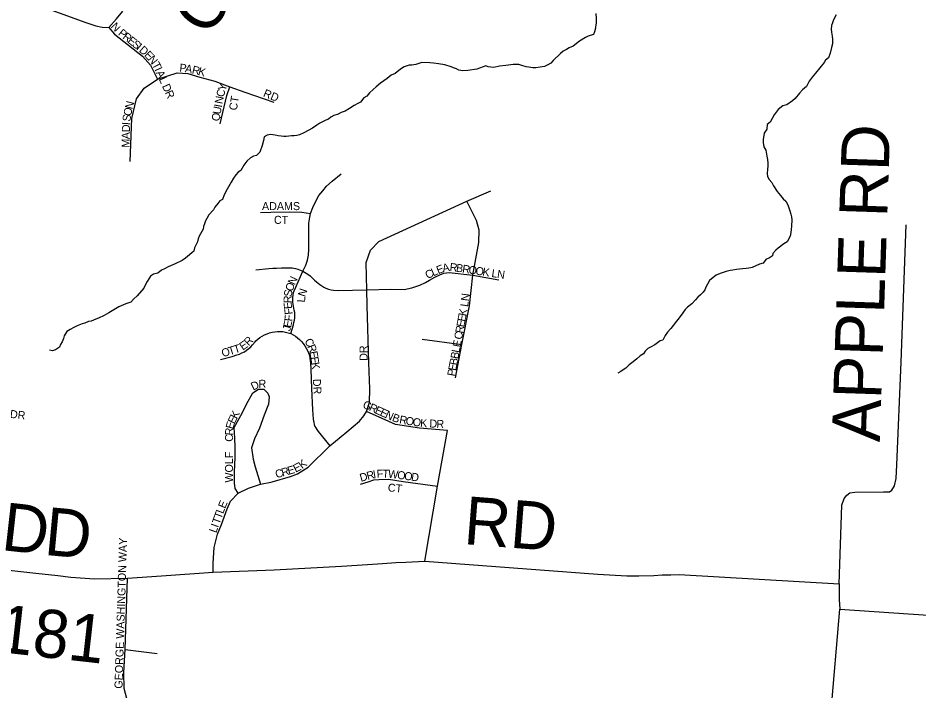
# Model space of a CAD drawing. Extents: x 1310247 to 1664935, y 235267 to 584339.
# Drawn here: x 1479257 to 1484885, y 386965 to 391172 of the extents above; entities that cross this region are included whole.
import ezdxf

# ---------------------------------------------------------------- set-up
doc = ezdxf.new("R2010")
doc.units = 0
for name, color, linetype in [('GM_X_County_Road', 7, 'Continuous'), ('GM_X_County_Road_Text', 7, 'Continuous'), ('GM_X_Minor_River', 7, 'Continuous'), ('GM_X_Township_Road', 7, 'Continuous'), ('GM_X_Township_Road_Text', 7, 'Continuous'), ('GM_X_Township_Subdivision', 7, 'Continuous'), ('GM_X_Township_Subdivision_Text', 7, 'Continuous')]:
    doc.layers.add(name, color=color, linetype=linetype)

msp = doc.modelspace()

# ---------------------------------------------------------------- linework, layer by layer
at = {"layer": 'GM_X_County_Road'}
msp.add_lwpolyline([(1479347, 391264), (1479681.3, 391144.1), (1479744.4, 391123.4), (1479782.5, 391114.5), (1479823.8, 391111.7), (1479871.9, 391165.9), (1479912.2, 391215.7)], dxfattribs=at)
at = {"layer": 'GM_X_Minor_River'}
for points in [[(1482866.9, 391201.2), (1482868.4, 391169), (1482867.9, 391141), (1482863.3, 391100.9), (1482859, 391084.9), (1482852.7, 391069), (1482818.4, 391057.5), (1482802.2, 391049.8), (1482765.7, 391026.3), (1482725, 390995), (1482700.7, 390985.3), (1482682.5, 390975.6), (1482662.2, 390963.9), (1482645.9, 390950.2), (1482601.1, 390906.8), (1482584.7, 390889), (1482566.5, 390879.3), (1482546.2, 390869.6), (1482518, 390864.1), (1482491.9, 390860.6), (1482473.8, 390860.9), (1482447.8, 390865.3), (1482431.8, 390867.6)], [(1484368.3, 391192.9), (1484351.7, 391161.1), (1484345.3, 391141.1), (1484339.1, 391125.2), (1484336.7, 391103.1), (1484338.3, 391083), (1484344, 391058.9), (1484345.6, 391038.8), (1484345.2, 391010.7), (1484338.8, 390988.7), (1484330.1, 390952.7), (1484319.6, 390922.8), (1484301.3, 390909.1), (1484293, 390893.2), (1484266.4, 390861.5), (1484239.7, 390827.9), (1484217.2, 390802.2), (1484198.7, 390776.4), (1484182.1, 390744.6), (1484157.7, 390723), (1484139.2, 390701.2), (1484112.6, 390669.5), (1484096.3, 390653.8), (1484059.8, 390630.3), (1484035.6, 390622.7), (1484005, 390599.2), (1483980.4, 390567.5), (1483955.6, 390521.8), (1483937.2, 390506), (1483934.8, 390478), (1483918.3, 390452.2), (1483911.6, 390412.2), (1483911.3, 390394.1), (1483916.8, 390365.9), (1483928.5, 390345.6), (1483935.9, 390307.4), (1483939.6, 390287.2), (1483941.2, 390265.1), (1483940.9, 390247.1), (1483938.6, 390225), (1483936.1, 390201), (1483939.8, 390180.8), (1483949.5, 390162.6), (1483965.3, 390144.3), (1483977, 390122), (1484000.5, 390087.5), (1484020.1, 390063), (1484037.9, 390042.6), (1484053.7, 390026.3), (1484065.3, 390004), (1484078.8, 389967.7), (1484084.4, 389945.5), (1484088.2, 389929.4), (1484091.9, 389911.2)], [(1482431.8, 390867.6), (1482403.8, 390876.1), (1482385.8, 390880.5), (1482349.7, 390881.1), (1482305.5, 390875.9), (1482265.2, 390870.6), (1482229, 390863.2), (1482210.9, 390865.5), (1482194.9, 390867.8), (1482178.9, 390872.1), (1482162.8, 390866.3), (1482140.6, 390858.7), (1482122.4, 390853), (1482068.1, 390843.9), (1482035.9, 390842.5), (1482011.9, 390846.9), (1481996, 390855.2), (1481978, 390861.5), (1481962.1, 390867.8), (1481924.1, 390878.5), (1481884.1, 390885.3), (1481852, 390889.8), (1481830, 390892.2), (1481779.8, 390893.1), (1481761.7, 390887.4), (1481741.5, 390881.8), (1481717.4, 390878.2), (1481701.3, 390876.4), (1481669, 390867), (1481646.6, 390851.3), (1481614.1, 390825.8), (1481587.8, 390814.2), (1481563.4, 390794.6), (1481543.1, 390778.9), (1481520.7, 390765.2), (1481494.3, 390741.6), (1481475.9, 390725.9), (1481453.5, 390704.2), (1481437.1, 390684.4), (1481416.8, 390672.7), (1481396.3, 390645), (1481380.1, 390637.2), (1481357.8, 390625.6), (1481327.4, 390606), (1481301, 390590.5), (1481276.8, 390580.8), (1481256.5, 390571.2), (1481230.3, 390561.6), (1481212.1, 390551.9), (1481195.8, 390540.1), (1481179.6, 390534.4), (1481143.2, 390515), (1481124.9, 390501.2), (1481096.5, 390483.7), (1481041.8, 390454.5), (1481015.5, 390440.9), (1480999.4, 390437.2), (1480983.3, 390435.5), (1480965.2, 390435.8), (1480949.1, 390434.1), (1480933, 390430.3), (1480916.9, 390430.6), (1480900.9, 390432.9), (1480882.9, 390435.2), (1480862.9, 390439.6), (1480834.9, 390444.1), (1480812.7, 390440.5), (1480794.5, 390428.8), (1480790.1, 390406.8), (1480781.5, 390374.8), (1480768.8, 390332.9), (1480746.4, 390313.2), (1480728.2, 390307.5), (1480710, 390297.8), (1480687.6, 390278.1), (1480667.1, 390252.4), (1480648.4, 390218.6), (1480632.2, 390208.8), (1480617.9, 390191), (1480603.5, 390171.2), (1480589, 390145.4), (1480564.2, 390101.7), (1480545.5, 390065.9), (1480535, 390038), (1480518.8, 390028.2), (1480506.5, 390012.4), (1480486, 389988.6), (1480477.7, 389972.7), (1480449.1, 389941.1), (1480436.7, 389919.3), (1480428.4, 389903.4), (1480422, 389885.4), (1480415.8, 389869.5), (1480413.4, 389851.4), (1480388.6, 389807.7), (1480382.3, 389791.8), (1480378, 389773.8), (1480359.3, 389736), (1480354.9, 389714), (1480304, 389670.7), (1480283.7, 389657)], [(1484091.9, 389911.2), (1484089.2, 389871.1), (1484086.8, 389849.1), (1484084.5, 389831.1), (1484080.1, 389809.1), (1484061.4, 389773.3), (1484041.1, 389759.6), (1484006.6, 389734.1), (1483990.3, 389720.3), (1483971.9, 389700.6), (1483969.6, 389684.6), (1483951.4, 389672.8), (1483929.1, 389663.2), (1483912.7, 389639.4), (1483888.5, 389633.8), (1483844, 389612.5), (1483821.8, 389608.9), (1483805.7, 389607.2), (1483783.6, 389603.5), (1483763.5, 389601.9), (1483745.4, 389600.2), (1483723.3, 389596.6), (1483705.1, 389592.9), (1483681, 389587.3), (1483642.6, 389575.9), (1483618.3, 389564.3), (1483600, 389550.6), (1483577.6, 389530.9), (1483565.2, 389509), (1483556.9, 389493.1), (1483548.6, 389473.2), (1483536.3, 389457.3), (1483519.9, 389441.6), (1483503.6, 389427.8), (1483489.3, 389410), (1483466.8, 389386.3), (1483440.4, 389364.7), (1483424, 389348.9), (1483409.7, 389329.1), (1483387, 389297.4), (1483370.6, 389277.6), (1483335.8, 389232.1), (1483315.3, 389208.3), (1483298.9, 389186.5), (1483284.3, 389158.7), (1483268.2, 389153), (1483251.9, 389141.2), (1483235.7, 389129.5), (1483213.4, 389115.8), (1483191.1, 389106.1), (1483174.8, 389090.4), (1483164.5, 389072.5), (1483144.2, 389060.8), (1483123.8, 389041.1), (1483099.4, 389023.5), (1483075, 389003.8), (1483054.6, 388984.1), (1483038.3, 388972.4), (1483022.1, 388962.6), (1483003.9, 388950.9)], [(1480283.7, 389657), (1480239.2, 389635.7), (1480194.7, 389616.5), (1480172.5, 389604.8), (1480154.2, 389595.1), (1480129.8, 389577.5), (1480103.6, 389569.9), (1480085.3, 389558.2), (1480064.7, 389524.4), (1480050.2, 389498.6), (1480043.9, 389482.6), (1480001, 389435.2), (1479978.6, 389415.5), (1479962.2, 389395.8), (1479929.9, 389384.3), (1479887.4, 389367), (1479855, 389347.5), (1479824.6, 389330), (1479796.2, 389312.4), (1479759.8, 389295), (1479743.6, 389289.2), (1479713.3, 389277.7), (1479697.2, 389274), (1479674.9, 389264.3), (1479658.8, 389260.6), (1479626.5, 389247.1), (1479606.2, 389237.5), (1479584, 389225.8), (1479561.7, 389212.1), (1479545.2, 389186.3), (1479540.9, 389168.3), (1479532.5, 389148.4), (1479522.1, 389130.5), (1479515.9, 389114.6), (1479491.5, 389097), (1479473.3, 389091.3), (1479453.3, 389095.6)]]:
    msp.add_lwpolyline(points, dxfattribs=at)
at = {"layer": 'GM_X_Township_Road'}
for points in [[(1484780.1, 389193.5), (1484805.2, 389879.7)], [(1484386.5, 387635.4), (1484404.4, 388126.5), (1484417.5, 388168.2), (1484434, 388189.8), (1484454.4, 388203.3), (1484484.5, 388208.5), (1484664.6, 388209.9), (1484700.6, 388211), (1484716.8, 388220.5), (1484731.6, 388248.2), (1484742.8, 388294), (1484747, 388378), (1484773.8, 389020.4), (1484780.1, 389193.5)], [(1478444.4, 387802.8), (1479367.8, 387702.4), (1479506.6, 387686.1), (1479587, 387677.5), (1479734.3, 387666), (1479942, 387670.8), (1480152.6, 387685.1), (1480477.1, 387707.1), (1480856.6, 387721.8), (1481277.2, 387745.3), (1481440.5, 387755.1), (1481534.4, 387762.9), (1481616.6, 387768.7), (1481679.2, 387770.7), (1481797.6, 387777.6), (1482879.4, 387696.4), (1483060.4, 387684.6), (1483134.7, 387684.6), (1483229.6, 387687.6), (1483280.5, 387690.5), (1483335.3, 387690.5), (1483388.1, 387693.5), (1484386.5, 387635.4), (1484387.4, 387537.9), (1484390.1, 387477.3), (1485065.8, 387430.4)], [(1484334.1, 386817.2), (1484390.1, 387477.3)]]:
    msp.add_lwpolyline(points, dxfattribs=at)
at = {"layer": 'GM_X_Township_Subdivision'}
for points in [[(1479823.8, 391111.7), (1479860.2, 391070.3), (1480035.2, 390934.5), (1480085.5, 390877.4), (1480128, 390789.1)], [(1479957.6, 390274.9), (1479968.1, 390543.1), (1479998.3, 390666.1), (1480046.4, 390733.2), (1480128, 390789.1), (1480252, 390829.5), (1480318, 390824.9), (1480393.8, 390802.2), (1480487.5, 390777.3), (1480580.1, 390741.8), (1480674.8, 390707.6), (1480856.2, 390645.8)], [(1480520.5, 390510.7), (1480560.8, 390687.3), (1480580.1, 390741.8)], [(1480960.5, 389199.4), (1480977.2, 389253.2), (1480981, 389268.5), (1480983.4, 389282.4), (1480985.5, 389297.4), (1480986.6, 389308.7), (1480986.6, 389317.8), (1480985.8, 389330.7), (1480983.1, 389346), (1480978.6, 389369.9), (1480976.1, 389381.4), (1480974.3, 389396.9), (1480973.7, 389408.4), (1480973.7, 389424), (1480975.4, 389439), (1480979.1, 389455.7), (1480982.9, 389466.9), (1480992.2, 389490.5), (1481037.1, 389588.6), (1481055.2, 389627), (1481065.8, 389658.3), (1481071.8, 389688.6), (1481074.9, 389725), (1481074.9, 389775), (1481073.4, 389823.4), (1481073.4, 389858.3), (1481074.9, 389890.1), (1481080.4, 389926.9), (1481085.4, 389949.3), (1481099.1, 389986.6), (1481123.3, 390039.5), (1481137, 390062.3), (1481161.2, 390092.6), (1481185.3, 390120.6), (1481219.2, 390152.2), (1481276.3, 390197.1)], [(1480836, 388271.1), (1480845.8, 388273.1), (1480959.2, 388305.6), (1481003.9, 388322.2), (1481069.3, 388364.2), (1481205.9, 388496.9), (1481311.5, 388585.4), (1481390.3, 388652.2), (1481418.5, 388685), (1481433.7, 388712.6), (1481452.8, 388769.5), (1481454.4, 388854.1), (1481449.8, 389016.3), (1481439, 389375.4), (1481435.8, 389472.4), (1481433.6, 389556.1), (1481432.8, 389643.8), (1481459.7, 389720.7), (1481511.3, 389775.3), (1482061.9, 390027.9), (1482211.5, 390091.6)], [(1481990.3, 388922.4), (1482029.2, 389131), (1482078.3, 389372.4), (1482098.4, 389563.6), (1482135.6, 389769.3), (1482138.8, 389846.1), (1482121.2, 389906.3), (1482061.9, 390027.9)], [(1480771.2, 389956.5), (1480836.7, 389957.4), (1480954.6, 389961), (1481029.4, 389958.7), (1481085.4, 389949.3)], [(1480743.8, 389598.2), (1480823.2, 389605.4), (1480848.7, 389607.4), (1480872.1, 389608.4), (1480902.3, 389609.4), (1480931.5, 389610.4), (1480956.9, 389610.8), (1480970.5, 389610.1), (1480981, 389608.7), (1480991.2, 389606.4), (1481006.1, 389601.6), (1481025.5, 389593.8), (1481037.1, 389588.6), (1481057.4, 389576.8), (1481068.2, 389570.1), (1481082.5, 389559.6), (1481090.3, 389551.9), (1481098.1, 389544.3), (1481109.3, 389534.1), (1481121.5, 389522.2), (1481131.7, 389513.7), (1481142.2, 389505.6), (1481155.4, 389496.8), (1481168.7, 389488.6), (1481180.6, 389483.2), (1481195.8, 389477.8), (1481212.5, 389473.3), (1481227.1, 389470.6), (1481262.1, 389469.1), (1481431.2, 389472.3), (1481435.8, 389472.4), (1481583.8, 389476.2), (1481669, 389475.7), (1481716.4, 389484.5), (1481767.7, 389502.1), (1481803.5, 389519.7), (1481827.4, 389533.9), (1481861.7, 389551), (1481892.5, 389566.6), (1481916.4, 389576.4), (1481950.7, 389581.8), (1482098.4, 389563.6), (1482261, 389534.3)], [(1480522.5, 389037.5), (1480595, 389056.8), (1480624.2, 389066.1), (1480640.3, 389071.5), (1480656, 389078.2), (1480671.1, 389086.2), (1480685.4, 389095.5), (1480698.9, 389105.9), (1480711.5, 389117.4), (1480723.1, 389129.9), (1480738.3, 389147.6), (1480742.9, 389153), (1480755.2, 389164.4), (1480768.5, 389174.7), (1480782.5, 389183.9), (1480797.3, 389192), (1480812.7, 389198.8), (1480828.5, 389204.3), (1480844.8, 389208.5), (1480861.4, 389211.3), (1480878.1, 389212.7), (1480894.9, 389212.8), (1480911.7, 389211.5), (1480928.3, 389208.8), (1480944.6, 389204.7), (1480960.5, 389199.4), (1480975.6, 389191.7), (1480990.1, 389182.9), (1481003.8, 389173), (1481016.7, 389162), (1481028.6, 389150), (1481039.6, 389137.1), (1481049.4, 389123.4), (1481058.2, 389108.9), (1481065.7, 389093.8), (1481072.1, 389078.1), (1481077.2, 389061.9), (1481080.9, 389045.4), (1481083.9, 389012.1), (1481085.7, 388977.4), (1481090.8, 388855.3), (1481096, 388723.3), (1481100.7, 388664.1), (1481104.3, 388643.1), (1481107.4, 388630.9), (1481111.8, 388619), (1481116.9, 388609.9), (1481123.2, 388600), (1481132.3, 388587.4), (1481205.9, 388496.9)], [(1481781.6, 389163.8), (1482029.2, 389131)], [(1480632.6, 388202.1), (1480614, 388231.4), (1480609.1, 388266.6), (1480609.1, 388334.1), (1480614, 388424.1), (1480613, 388489.7), (1480611, 388546.4), (1480608.1, 388611.7), (1480660, 388706.8), (1480684.4, 388757.7), (1480723.5, 388828.1), (1480759.2, 388851.8), (1480793.9, 388851), (1480817.7, 388827.1), (1480825.3, 388804.6), (1480822.3, 388757.7), (1480795.9, 388689.2), (1480765.6, 388608), (1480734.3, 388540.5), (1480716.7, 388484.8), (1480725.5, 388415.3), (1480738.2, 388367.4), (1480771.5, 388257.9)], [(1481797.6, 387777.6), (1481877.2, 388245.7), (1481939.4, 388594.3), (1481765, 388608.4), (1481615, 388631.3), (1481574.6, 388650), (1481433.7, 388712.6)], [(1481396.5, 388258.8), (1481445.4, 388273.5), (1481480.7, 388284.3), (1481511, 388288.2), (1481571.6, 388289.2), (1481662.6, 388275.4), (1481877.2, 388245.7)], [(1480477.1, 387707.1), (1480476.1, 387763.9), (1480481.9, 387861.7), (1480502.5, 387944.8), (1480527.9, 388005.5), (1480563.1, 388103.3), (1480584.7, 388151.3), (1480632.6, 388202.1), (1480696.2, 388232.4), (1480771.5, 388257.9), (1480836, 388271.1)], [(1479826.2, 385717.6), (1480042.5, 385718.6), (1480105.8, 385722.2), (1480139.1, 385738.7), (1480156.4, 385765.5), (1480169.8, 385814.3), (1480174.5, 385884.1), (1480176.5, 386164.5), (1480188, 386466), (1480184.1, 386519.6), (1480176.5, 386563.6), (1480125.6, 386640.3), (1480045.4, 386744.4), (1479986, 386815.3), (1479944.9, 386887), (1479921, 386980.8), (1479919.1, 387080.3), (1479926.7, 387224.8), (1479942, 387670.8)], [(1479926.7, 387224.8), (1480125.8, 387200.2)]]:
    msp.add_lwpolyline(points, dxfattribs=at)

# ---------------------------------------------------------------- texts
at = {"layer": 'GM_X_County_Road_Text'}
msp.add_text('C', height=300, rotation=53.7772, dxfattribs=at).set_placement((1480436.3, 391044.2))
at = {"layer": 'GM_X_Township_Road_Text'}
for s, rotation, p in [('APPLE RD', 88.105, (1484640.4, 388519.1)), ('RD', 355.5641, (1482035.8, 387884)), ('D', 353.5785, (1479146.6, 387847)), ('D', 354.6233, (1479414.8, 387816.9)), ('T-181', 353.5488, (1478741.1, 387253.5))]:
    msp.add_text(s, height=300, rotation=rotation, dxfattribs=at).set_placement(p)
at = {"layer": 'GM_X_Township_Subdivision_Text'}
for s, rotation, p in [('N', 312.7736, (1479833.8, 391116.3)), ('P', 320.5216, (1479878.8, 391070)), ('R', 321.4756, (1479906.6, 391047)), ('E', 321.4469, (1479937.6, 391022.3)), ('S', 321.478, (1479965.2, 391000.4)), ('I', 321.4426, (1479992.7, 390978.5)), ('D', 319.4082, (1480009.5, 390965.1)), ('E', 314.3046, (1480042.1, 390937.2)), ('N', 309.4586, (1480066, 390912.9)), ('T', 297.5791, (1480092.4, 390881.2)), ('I', 294.6285, (1480108.4, 390850.6)), ('P', 354.2055, (1480263.9, 390837.4)), ('A', 350.2409, (1480298, 390833.9)), ('R', 346.2763, (1480340.5, 390826.7)), ('K', 344.2939, (1480378.5, 390817.4)), ('A', 294.3752, (1480117.5, 390830.6)), ('L', 294.3535, (1480135.7, 390790.6)), ('D', 294.3553, (1480155.7, 390746.5)), ('Y', 71.9589, (1480551.9, 390711.7)), ('R', 294.382, (1480173.8, 390706.4)), ('C', 75.4455, (1480542.2, 390674.2)), ('RD', 337.6225, (1480785, 390683.3)), ('N', 75.3861, (1479972.3, 390598.8)), ('N', 79.1359, (1480534.1, 390631.8)), ('CT', 80.5416, (1480623.8, 390591.6)), ('O', 77.5937, (1479963, 390556.3)), ('U', 79.4903, (1480522, 390567)), ('I', 79.5137, (1480530.1, 390610.2)), ('S', 82.0088, (1479958.3, 390522.4)), ('Q', 79.4703, (1480514, 390523.7)), ('D', 88.6316, (1479956, 390458)), ('I', 86.424, (1479957, 390501.5)), ('A', 88.6316, (1479954.9, 390414)), ('M', 88.6316, (1479953.7, 390361.3)), ('ADAMS', 0, (1480781.4, 389971.2)), ('CT', 0, (1480856.2, 389885.2)), ('E', 21.5731, (1481882.2, 389570.4)), ('A', 11.3742, (1481912.7, 389582.7)), ('R', 353.8207, (1481951.8, 389591.2)), ('B', 351.5437, (1481990.7, 389587)), ('R', 351.396, (1482029.8, 389581.2)), ('C', 26.0981, (1481815.5, 389539)), ('L', 24.1206, (1481850.7, 389556.2)), ('O', 351.4001, (1482069, 389575.2)), ('O', 351.4102, (1482112.5, 389568.7)), ('K', 351.42, (1482156, 389562.1)), ('L', 351.3992, (1482212.6, 389553.5)), ('N', 351.4102, (1482247.4, 389548.3)), ('O', 69.201, (1480970.8, 389458.9)), ('N', 65.9576, (1480986.1, 389499.4)), ('S', 82.0515, (1480966.7, 389426.9)), ('N', 71.4268, (1481050.9, 389425.2)), ('R', 89.0286, (1480966.1, 389388.9)), ('L', 88.6068, (1481050.7, 389393.9)), ('N', 82.5191, (1482073.5, 389399.9)), ('E', 96.4714, (1480970, 389355.7)), ('F', 96.4593, (1480974, 389320.7)), ('K', 79.3374, (1482057.3, 389305.9)), ('L', 81.3842, (1482068.1, 389364)), ('F', 84.3007, (1480970.6, 389274.1)), ('E', 79.3682, (1482050.8, 389271.3)), ('J', 77.2151, (1480957.1, 389211.6)), ('E', 77.6248, (1480962, 389233.4)), ('R', 79.352, (1482037, 389197.8)), ('E', 79.3384, (1482044.3, 389236.7)), ('R', 45.6937, (1480698.2, 389119.1)), ('C', 79.352, (1482029.7, 389158.8)), ('T', 17.0188, (1480578.9, 389064.2)), ('T', 17.0188, (1480612.6, 389074.5)), ('E', 35.0718, (1480661.6, 389092.3)), ('C', 299.6726, (1481044.7, 389152.7)), ('R', 291.824, (1481063.5, 389119.9)), ('DR', 90, (1481440.8, 389029)), ('E', 79.3384, (1482020.7, 389111.2)), ('O', 17.0111, (1480536.9, 389051.3)), ('E', 280.0238, (1481077.5, 389085.8)), ('B', 79.352, (1482006.9, 389037.7)), ('L', 79.3682, (1482014.2, 389076.6)), ('E', 278.6132, (1481083.5, 389051.4)), ('K', 278.6169, (1481088.8, 389016.6)), ('E', 79.3384, (1481993.1, 388964.2)), ('B', 79.3678, (1481999.6, 388998.8)), ('P', 79.3652, (1481986.6, 388929.6)), ('D', 25.6363, (1480726.2, 388842.3)), ('R', 0.4615, (1480760.3, 388860.1)), ('DR', 273.0116, (1481098.8, 388915.1)), ('ROCKWOOD DR', 353.4796, (1478780.5, 388721.6)), ('G', 335.4584, (1481405.8, 388738.4)), ('R', 335.4586, (1481445.8, 388720.1)), ('E', 335.4671, (1481481.9, 388703.6)), ('E', 335.4634, (1481513.9, 388689)), ('E', 64.1925, (1480609.5, 388630.4)), ('K', 63.2981, (1480624.8, 388661.9)), ('N', 335.4584, (1481545.9, 388674.4)), ('B', 340.5014, (1481590.4, 388654.3)), ('R', 350.0104, (1481636.5, 388638.8)), ('O', 350.3881, (1481675.8, 388631.8)), ('O', 351.0472, (1481719.8, 388624.4)), ('E', 74.7377, (1480601.1, 388598.8)), ('K', 355.7023, (1481767.7, 388617)), ('D', 356.9866, (1481826, 388613)), ('R', 356.9987, (1481869.9, 388610.6)), ('C', 89.5628, (1480600.4, 388522.9)), ('R', 88.7615, (1480600.7, 388562.4)), ('WOLF', 90, (1480600.4, 388267.8)), ('E', 26.6179, (1480991.3, 388329.5)), ('K', 38.1468, (1481032, 388351.1)), ('C', 15.8153, (1480871.7, 388294.6)), ('R', 15.8219, (1480909.8, 388305.4)), ('E', 15.8307, (1480947.9, 388316.2)), ('R', 14.7077, (1481441.6, 388284)), ('I', 9.6205, (1481478.7, 388293.8)), ('F', 2.9252, (1481498.9, 388297.4)), ('T', 358.9345, (1481533.1, 388299.1)), ('W', 353.8678, (1481567.1, 388298.6)), ('O', 352.2378, (1481623.6, 388292.5)), ('O', 352.248, (1481667.2, 388286.5)), ('D', 15.2609, (1481399.2, 388272.5)), ('D', 352.2378, (1481710.8, 388280.6)), ('CT', 353.9946, (1481565.4, 388213.7)), ('E', 67.275, (1480550.8, 388102.2)), ('T', 70.114, (1480514.8, 388003.6)), ('T', 70.114, (1480526.8, 388036.7)), ('L', 69.6294, (1480538.7, 388069.7)), ('I', 70.114, (1480507.3, 387982.9)), ('L', 70.1219, (1480495.4, 387949.8)), ('GEORGE WASHINGTON WAY', 88.2097, (1479909.6, 386979))]:
    msp.add_text(s, height=50, rotation=rotation, dxfattribs=at).set_placement(p)

doc.saveas('drawing.dxf')
